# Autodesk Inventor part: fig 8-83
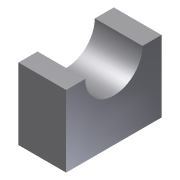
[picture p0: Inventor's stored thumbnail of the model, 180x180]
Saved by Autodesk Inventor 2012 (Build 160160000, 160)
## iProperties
Shininess: 77.0
Length Units: 11269
Angle Units: 11279
Time Units: 11290
Mass Units: 11283
Length Display Precision: 3
Angle Display Precision: 2
Created: 2002-01
Part Number: fig 8-83
Document SubType Name: Modeling
Designer: ***
Density: 1 g/cm^3
Material: Default
Density: 0.0
Volumn: 0.0
Area: 0.0
PropertySet Name: Model Information
Control State: 0
Master: False
Checked Out: False
Author: ***
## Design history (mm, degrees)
sketch "Sketch5"
  geometry: L1 (-22.226, 10.275)-(-14.226, 10.275); L2 (9.774, 10.275)-(17.774, 10.275); L3 (17.774, 10.275)-(17.774, -19.725); L4 (17.774, -19.725)-(-22.226, -19.725); L5 (-22.226, -19.725)-(-22.226, 10.275); A1 r 12 centre (-2.226, 10.275) between (-14.226, 10.275) and (9.774, 10.275)
  constraints: 10 end point, 2 equal length, 2 parallel, 2 point on circle, 1 centre point, 1 collinear, 1 horizontal, 1 perpendicular, 1 point on line
  dimensions: "d7" = 40 distance of L3.end L4.end; "d8" = 30 distance of L2.end L3.end; "d9" = 12 radius of A1
extrude "Extrusion2" new body sketch "Sketch5" distance "d10" = 20; taper "d11" = 0 deg
workplane "Work Plane3"
sketch "Sketch6"
  geometry: L1 (19.321, -18.091)-(12.314, -18.091); L2 (12.314, -18.091)-(12.314, -11.217); L3 (12.314, -11.217)-(7.026, -11.217); L4 (7.026, -11.217)-(7.026, 7.425); L5 (7.026, 7.425)-(7.026, 14.035); L6 (7.026, 14.035)-(-10.029, 14.035)
  constraints: 12 end point, 4 parallel, 1 horizontal, 1 perpendicular
split "Split5" sketch "Sketch6"
body "Solid1"
other parameters: "d12" = 15
